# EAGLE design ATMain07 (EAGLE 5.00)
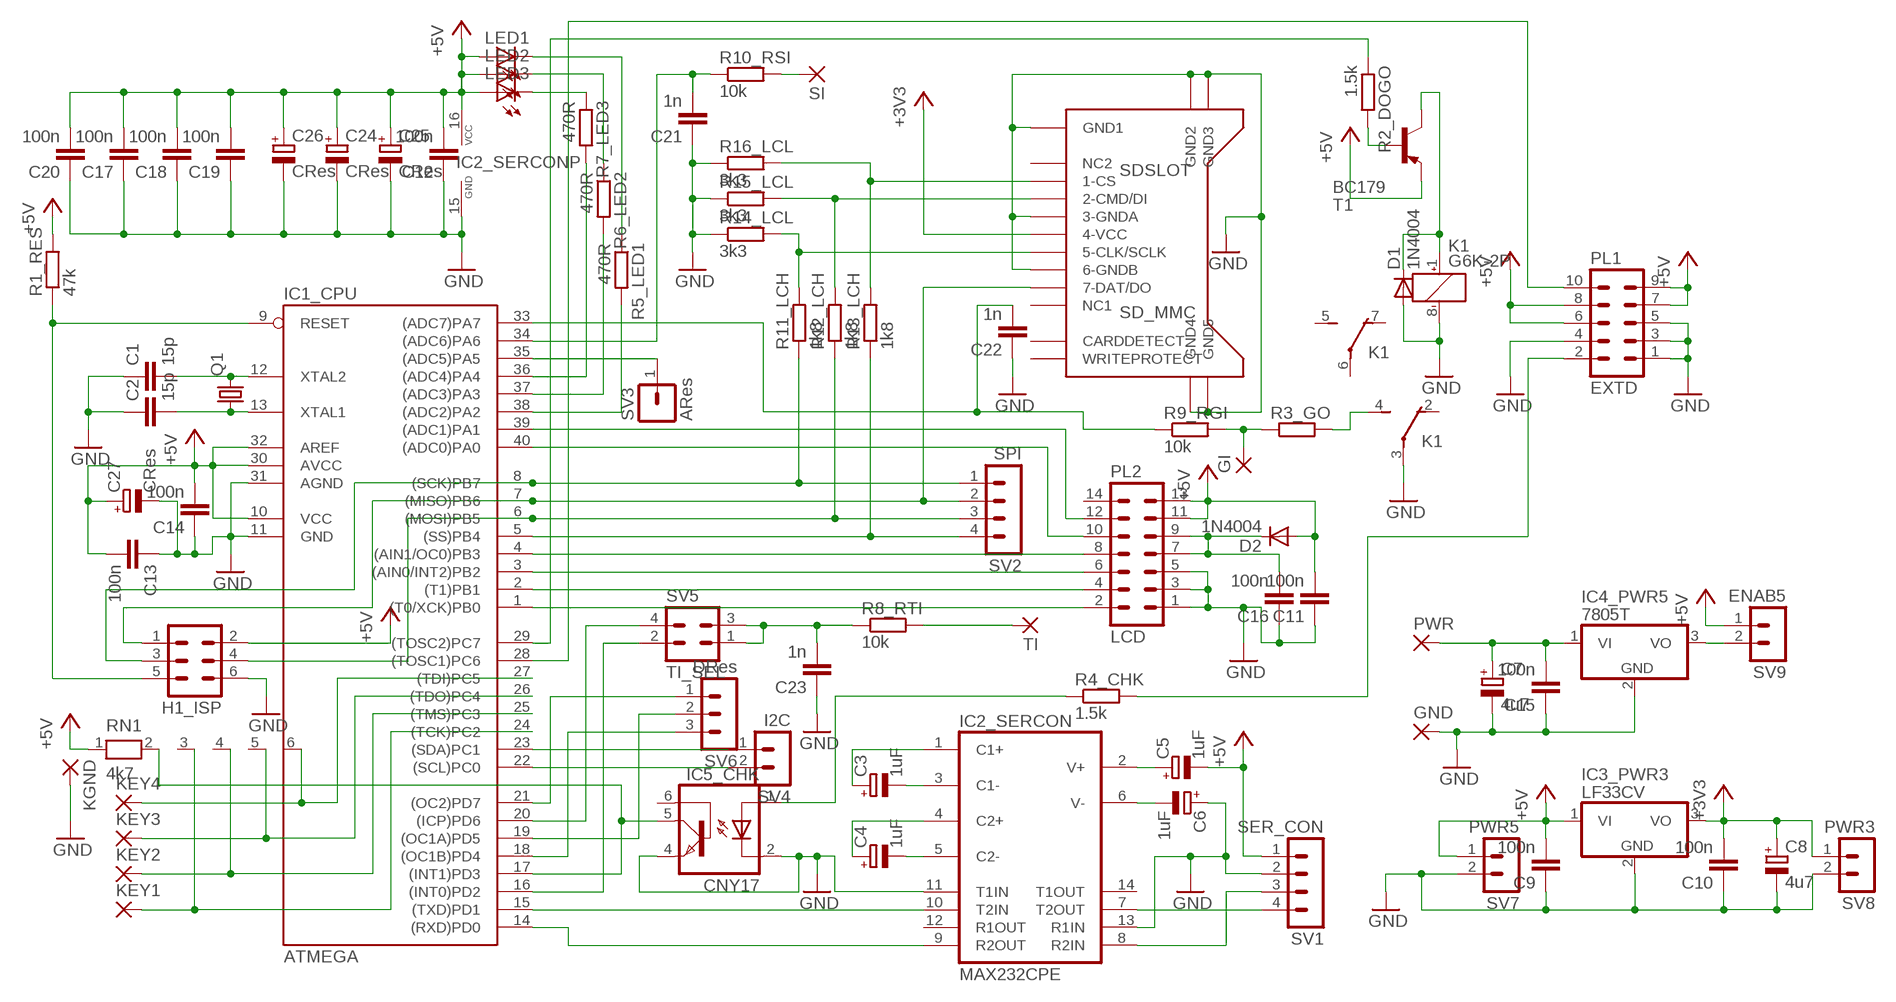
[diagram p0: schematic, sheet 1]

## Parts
C1  15p  C-EU025-025X050  [C025-025X050]
C2  15p  C-EU025-025X050  [C025-025X050]
C3  1uF  CPOL-EUE2-5  [E2-5]
C4  1uF  CPOL-EUE2-5  [E2-5]
C5  1uF  CPOL-EUE2-5  [E2-5]
C6  1uF  CPOL-EUE2-5  [E2-5]
C7  4u7  CPOL-EUE2-5  [E2-5]
C8  4u7  CPOL-EUE2-5  [E2-5]
C9  100n  C-EU025-025X050  [C025-025X050]
C10  100n  C-EU025-025X050  [C025-025X050]
C11  100n  C-EU025-025X050  [C025-025X050]
C12  100n  C-EU025-025X050  [C025-025X050]
C13  100n  C-EU025-025X050  [C025-025X050]
C14  100n  C-EU025-025X050  [C025-025X050]
C15  100n  C-EU025-025X050  [C025-025X050]
C16  100n  C-EU025-025X050  [C025-025X050]
C17  100n  C-EU025-025X050  [C025-025X050]
C18  100n  C-EU025-025X050  [C025-025X050]
C19  100n  C-EU025-025X050  [C025-025X050]
C20  100n  C-EU025-025X050  [C025-025X050]
C21  1n  C-EU025-025X050  [C025-025X050]
C22  1n  C-EU025-025X050  [C025-025X050]
C23  1n  C-EU025-025X050  [C025-025X050]
C24  CRes  CPOL-EUE2-5  [E2-5]
C25  CRes  CPOL-EUE2-5  [E2-5]
C26  CRes  CPOL-EUE2-5  [E2-5]
C27  CRes  CPOL-EUE2-5  [E2-5]
D1  1N4004  [DO41-10]
D2  1N4004  [DO41-10]
GI  2,54/1,0  [2,54/1,0]
GND  2,54/1,0  [2,54/1,0]
H1_ISP  MA03-2  [MA03-2]
IC1_CPU  ATMEGA  MEGA16-P  [DIL40]
IC2_SERCON  MAX232CPE  MAX232  [DIL16]
IC3_PWR3  LF33CV  7805T  [TO220H]
IC4_PWR5  7805T  [TO220H]
IC5_CHK  CNY17  [DIL06]
K1  G6K-2P  [G6K-2P]
KEY1  2,54/1,0  [2,54/1,0]
KEY2  2,54/1,0  [2,54/1,0]
KEY3  2,54/1,0  [2,54/1,0]
KEY4  2,54/1,0  [2,54/1,0]
KGND  2,54/1,0  [2,54/1,0]
LED1  BIGLED  [BIGLED]
LED2  BIGLED  [BIGLED]
LED3  BIGLED  [BIGLED]
PL1  EXTD  10V  [10V]
PL2  LCD  14V  [14V]
PWR  2,54/1,0  [2,54/1,0]
Q1  CRYTALHC49U-V  [HC49U-V]
R1_RES  47k  R-EU_0309/10  [0309/10]
R2_DOGO  1.5k  R-EU_0309/10  [0309/10]
R3_GO  R-EU_0309/10  [0309/10]
R4_CHK  1.5k  R-EU_0309/10  [0309/10]
R5_LED1  470R  R-EU_0309/10  [0309/10]
R6_LED2  470R  R-EU_0309/10  [0309/10]
R7_LED3  470R  R-EU_0309/10  [0309/10]
R8_RTI  10k  R-EU_0309/10  [0309/10]
R9_RGI  10k  R-EU_0309/10  [0309/10]
R10_RSI  10k  R-EU_0309/10  [0309/10]
R11_LCH  1k8  R-EU_0309/10  [0309/10]
R12_LCH  1k8  R-EU_0309/10  [0309/10]
R13_LCH  1k8  R-EU_0309/10  [0309/10]
R14_LCL  3k3  R-EU_0309/10  [0309/10]
R15_LCL  3k3  R-EU_0309/10  [0309/10]
R16_LCL  3k3  R-EU_0309/10  [0309/10]
RN1  4k7  RN05  [RN-6]
SDSLOT  SD_MMC  SD_MMCW_CARD  [SD_MMC-PACKAGE]
SI  2,54/1,0  [2,54/1,0]
SV1  SER_CON  MA04-1  [MA04-1]
SV2  SPI  MA04-1  [MA04-1]
SV3  ARes  MA01-1  [MA01-1]
SV4  I2C  MA02-1  [MA02-1]
SV5  TI_SEL  MA02-2  [MA02-2]
SV6  DRes  MA03-1  [MA03-1]
SV7  PWR5  MA02-1  [MA02-1]
SV8  PWR3  MA02-1  [MA02-1]
SV9  ENAB5  MA02-1  [MA02-1]
T1  BC179  [TO18]
TI  2,54/1,0  [2,54/1,0]

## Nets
+3V3: C8.+ C10.2 IC3_PWR3.3(VO) SDSLOT.P$4(4-VCC) SV8.1
+5V: C5.- C9.2 C11.2 C12.2 C13.2 C14.2 C17.2 C18.2 C19.2 C20.2 C24.+ C25.+ C26.+ C27.+ D2.A H1_ISP.2 IC1_CPU.10(VCC) IC1_CPU.30(AVCC) IC1_CPU.32(AREF) IC2_SERCON.16(VCC) IC3_PWR3.1(VI) LED1.A LED2.A LED3.A PL1.6 PL1.7 PL1.8 PL1.9 PL2.11 PL2.13 R1_RES.2 RN1.1 SV1.1 SV7.1 SV9.1 T1.1(E)
GND: C1.1 C2.1 C6.+ C7.- C8.- C9.1 C10.1 C11.1 C12.1 C13.1 C14.1 C15.1 C16.1 C17.1 C18.1 C19.1 C20.1 C21.1 C22.1 C23.1 C24.- C25.- C26.- C27.- D1.A GND.1(P) H1_ISP.6 IC1_CPU.11(GND) IC1_CPU.31(AGND) IC2_SERCON.11(T1IN) IC2_SERCON.13(R1IN) IC2_SERCON.15(GND) IC3_PWR3.2(GND) IC4_PWR5.2(GND) IC5_CHK.2(C) IC5_CHK.4(EMI) K1.3(2:P) K1.8(1:-) KGND.1(P) PL1.1 PL1.3 PL1.4 PL1.5 PL2.1 PL2.3 PL2.5 R14_LCL.1 R15_LCL.1 R16_LCL.1 SDSLOT.P$3(3-GNDA) SDSLOT.P$6(6-GNDB) SDSLOT.P$12(GND1) SDSLOT.P$13(GND2) SDSLOT.P$14(GND3) SDSLOT.P$15(GND4) SDSLOT.P$16(GND5) SV1.2 SV7.2 SV8.2
N$1: IC1_CPU.14((RXD)PD0) IC2_SERCON.9(R2OUT)
N$2: IC1_CPU.15((TXD)PD1) IC2_SERCON.10(T2IN)
N$3: IC4_PWR5.3(VO) SV9.2
N$4: IC1_CPU.37((ADC3)PA3) R6_LED2.2
N$5: IC1_CPU.38((ADC2)PA2) R5_LED1.2
N$6: C23.2 R8_RTI.1 SV5.1 SV5.3
N$7: C7.+ C15.2 IC4_PWR5.1(VI) PWR.1(P)
N$8: IC1_CPU.1((T0/XCK)PB0) PL2.2
N$9: IC1_CPU.2((T1)PB1) PL2.4
N$10: IC1_CPU.3((AIN0/INT2)PB2) PL2.6
N$11: IC1_CPU.4((AIN1/OC0)PB3) PL2.8
N$12: IC1_CPU.40((ADC0)PA0) PL2.10
N$13: IC1_CPU.39((ADC1)PA1) PL2.12
N$14: GI.1(P) R3_GO.1 R9_RGI.2
N$15: H1_ISP.1 IC1_CPU.7((MISO)PB6) SDSLOT.P$7(7-DAT/DO) SV2.2
N$16: H1_ISP.4 IC1_CPU.6((MOSI)PB5) R12_LCH.1 SV2.3
N$17: H1_ISP.3 IC1_CPU.8((SCK)PB7) R11_LCH.1 SV2.1
N$18: H1_ISP.5 IC1_CPU.9(RESET) R1_RES.1
N$19: LED3.K(C) R7_LED3.1
N$20: IC1_CPU.21((OC2)PD7) SV6.1
N$21: IC1_CPU.35((ADC5)PA5) SV3.1
N$22: IC1_CPU.16((INT0)PD2) SV5.2
N$23: IC1_CPU.20((ICP)PD6) SV5.4
N$24: IC1_CPU.27((TDI)PC5) KEY4.1(P) RN1.6
N$25: C21.2 IC1_CPU.34((ADC6)PA6) R10_RSI.1
N$27: K1.4(2:S) R3_GO.2
N$28: R10_RSI.2 SI.1(P)
N$29: IC1_CPU.26((TDO)PC4) KEY3.1(P) RN1.5
N$31: IC1_CPU.29((TOSC2)PC7) R2_DOGO.1
N$33: IC1_CPU.28((TOSC1)PC6) PL1.10
N$34: IC1_CPU.25((TMS)PC3) KEY2.1(P) RN1.4
N$35: IC1_CPU.24((TCK)PC2) KEY1.1(P) RN1.3
N$36: IC1_CPU.5((SS)PB4) R13_LCH.1 SV2.4
N$37: R11_LCH.2 R14_LCL.2 SDSLOT.P$5(5-CLK/SCLK)
N$38: C1.2 IC1_CPU.12(XTAL2) Q1.2
N$39: C2.2 IC1_CPU.13(XTAL1) Q1.1
N$41: R12_LCH.2 R15_LCL.2 SDSLOT.P$2(2-CMD/DI)
N$42: IC1_CPU.22((SCL)PC0) SV4.2
N$43: IC1_CPU.23((SDA)PC1) SV4.1
N$44: R8_RTI.2 TI.1(P)
N$45: IC1_CPU.36((ADC4)PA4) R7_LED3.2
N$46: R13_LCH.2 R16_LCL.2 SDSLOT.P$1(1-CS)
N$47: IC1_CPU.19((OC1A)PD5) SV6.2
N$48: IC1_CPU.18((OC1B)PD4) SV6.3
N$50: PL1.2 R4_CHK.2
N$51: C16.2 D2.C PL2.7 PL2.9
N$54: C3.+ IC2_SERCON.1(C1+)
N$55: C3.- IC2_SERCON.3(C1-)
N$56: C4.+ IC2_SERCON.4(C2+)
N$57: C4.- IC2_SERCON.5(C2-)
N$58: C5.+ IC2_SERCON.2(V+)
N$59: C6.- IC2_SERCON.6(V-)
N$60: C22.2 IC1_CPU.33((ADC7)PA7) R9_RGI.1
N$61: LED2.K(C) R6_LED2.1
N$62: R2_DOGO.2 T1.2(B)
N$63: D1.C K1.1(1:+) T1.3(C)
N$69: LED1.K(C) R5_LED1.1
N$70: IC2_SERCON.7(T2OUT) SV1.4
N$71: IC2_SERCON.8(R2IN) SV1.3
N$74: IC5_CHK.1(A) R4_CHK.1
N$75: IC1_CPU.17((INT1)PD3) IC5_CHK.5(COL) RN1.2
Unconnected: IC2_SERCON.12(R1OUT) IC2_SERCON.14(T1OUT) IC5_CHK.6(BAS) K1.2(2:O) K1.5(3:S) K1.6(3:P) K1.7(3:O) PL2.14 SDSLOT.P$8(NC1) SDSLOT.P$9(NC2) SDSLOT.P$10(CARDDETECT) SDSLOT.P$11(WRITEPROTECT)

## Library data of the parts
C1 C2 C9-C23 = smf:C-EU: CAPACITOR, European symbol
C3-C8 C24-C27 = smf:CPOL-EU: POLARIZED CAPACITOR, European symbol
D1 D2 = smf:1N4004: DIODE
GI GND KEY1-KEY4 KGND PWR SI TI = smf:2,54/1,0: THROUGH-HOLE PAD
H1_ISP = smf:MA03-2: PIN HEADER
IC1_CPU = smf:MEGA16-P: MICROCONTROLLER 16 Kbytes FLASH 1 kbytes SRAM 512 bytes EEPROM USART 8-channel 10 bit ADC Source: avr.lbr
IC2_SERCON = smf:MAX232: RS232 TRANSEIVER
IC3_PWR3 IC4_PWR5 = smf:78*: Positive VOLTAGE REGULATOR Source: http://cache.national.com/ds/LM/LM78L05.pdf http://www.fairchildsemi.com/ds/LM/LM7805.pdf
IC5_CHK = smf:CNY17: SIEMENS OPTO COUPLER
K1 = smf:G6K: Low Signal Relay oeiwcsnts1.omron.com/.. D20G6K0100.pdf
LED1-LED3 = smf:BIGLED: Big LED
PL1 = smf:10V: CONNECTOR
PL2 = smf:14V: CONNECTOR
Q1 = smf:CRYTAL: CRYSTAL
R1_RES R2_DOGO R3_GO R4_CHK R5_LED1 R6_LED2 R7_LED3 R8_RTI R9_RGI R10_RSI R11_LCH R12_LCH R13_LCH R14_LCL R15_LCL R16_LCL = smf:R-EU_: RESISTOR, European symbol
RN1 = smf:RN05: RESISTOR NETWORK
SDSLOT = smf:SD_MMC
SV1 SV2 = smf:MA04-1: PIN HEADER
SV3 = smf:MA01-1
SV4 SV7-SV9 = smf:MA02-1
SV5 = smf:MA02-2
SV6 = smf:MA03-1: PIN HEADER
T1 = smf:BC179: PNP Transistor

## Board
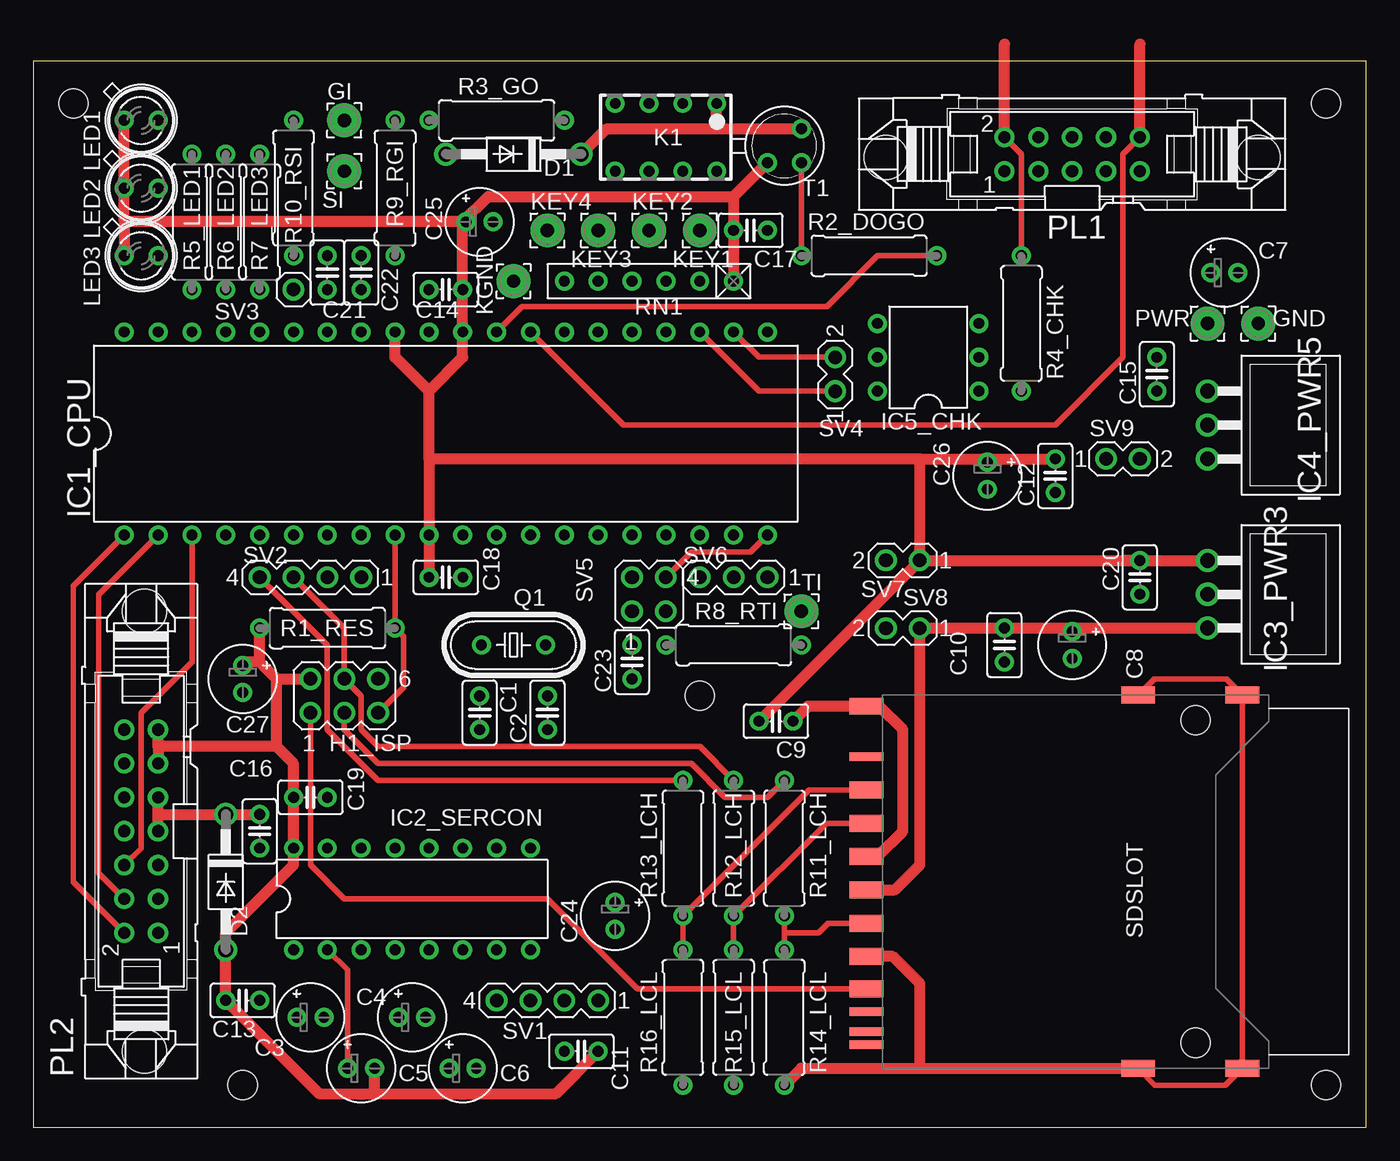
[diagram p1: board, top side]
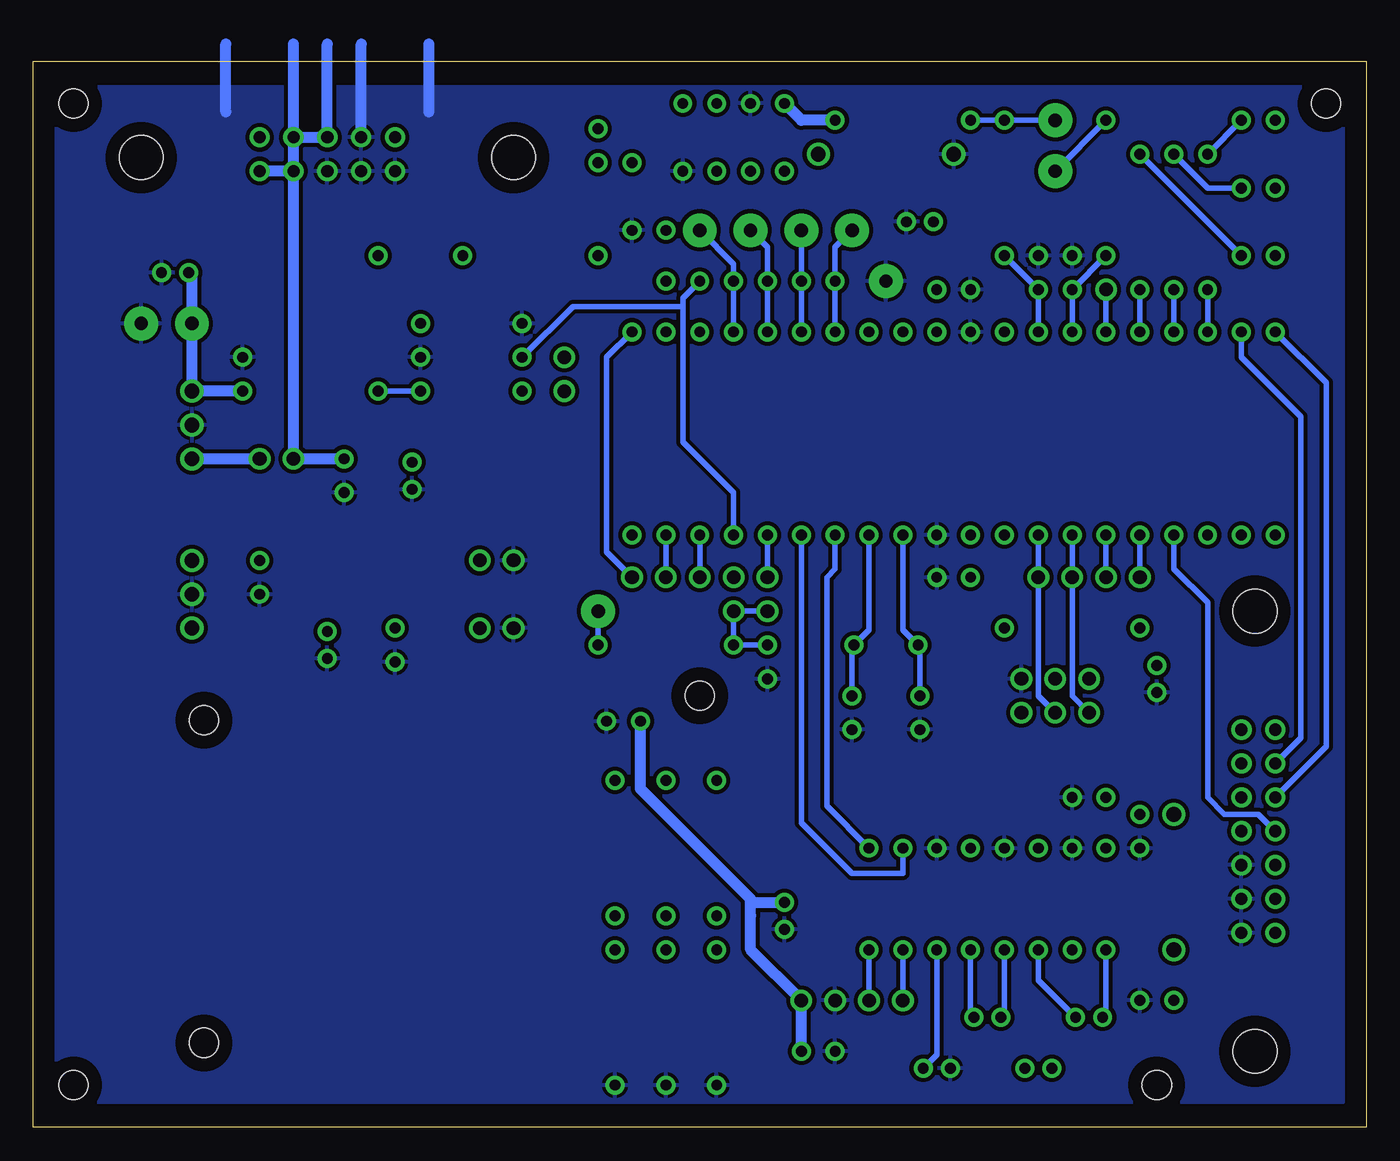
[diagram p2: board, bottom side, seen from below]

Size 100 x 80 mm. Coordinates in mm from the lower left corner, seen from the top.
Outline: 0,0 100,0 100,80 0,80 0,0
Copper layers (1*16): Top 0.035mm / dielectric 1.5mm / Bottom 0.035mm
Design rules "default *": minimum track width 16mil, minimum drill 24mil, track to track 12mil, track to pad 10mil, pad to pad 12mil, via to via 12mil, smd to smd 8mil, copper to edge 40mil, drill to drill 16mil, minimum pad ring 12mil, minimum via ring 8mil, stop-mask expansion 4mil, vias tented up to drill 0mil, thermal gap 10mil
Holes 2.2 mm at 15.71,3.17 3.01,76.83 50,32.38 96.99,3.17 96.99,76.83

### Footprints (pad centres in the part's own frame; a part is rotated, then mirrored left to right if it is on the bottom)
C025-025X050 = drill 0.813 round: 1 -1.27,0; 2 1.27,0
E2-5 = drill 0.813 pad 1.27 round: + -1.016,0; - 1.016,0
DO41-10 = drill 1.118 round: A 5.08,0; C -5.08,0
2,54/1,0 = drill 1 pad 2.54 round: 1 0,0
MA03-2 = drill 1.016 round: 1 -2.54,-1.27; 2 -2.54,1.27; 3 0,-1.27; 4 0,1.27; 5 2.54,-1.27; 6 2.54,1.27
DIL40 = drill 0.813 round: 1 -24.13,-7.62; 2 -21.59,-7.62; 3 -19.05,-7.62; 4 -16.51,-7.62; 5 -13.97,-7.62; 6 -11.43,-7.62; 7 -8.89,-7.62; 8 -6.35,-7.62; 9 -3.81,-7.62; 10 -1.27,-7.62; 11 1.27,-7.62; 12 3.81,-7.62; 13 6.35,-7.62; 14 8.89,-7.62; 15 11.43,-7.62; 16 13.97,-7.62; 17 16.51,-7.62; 18 19.05,-7.62; 19 21.59,-7.62; 20 24.13,-7.62; 21 24.13,7.62; 22 21.59,7.62; 23 19.05,7.62; 24 16.51,7.62; 25 13.97,7.62; 26 11.43,7.62; 27 8.89,7.62; 28 6.35,7.62; 29 3.81,7.62; 30 1.27,7.62; 31 -1.27,7.62; 32 -3.81,7.62; 33 -6.35,7.62; 34 -8.89,7.62; 35 -11.43,7.62; 36 -13.97,7.62; 37 -16.51,7.62; 38 -19.05,7.62; 39 -21.59,7.62; 40 -24.13,7.62
DIL16 = drill 0.813 round: 1 -8.89,-3.81; 2 -6.35,-3.81; 3 -3.81,-3.81; 4 -1.27,-3.81; 5 1.27,-3.81; 6 3.81,-3.81; 7 6.35,-3.81; 8 8.89,-3.81; 9 8.89,3.81; 10 6.35,3.81; 11 3.81,3.81; 12 1.27,3.81; 13 -1.27,3.81; 14 -3.81,3.81; 15 -6.35,3.81; 16 -8.89,3.81
TO220H = drill 1.118 round: 1 -2.54,-10.16; 2 0,-10.16; 3 2.54,-10.16
DIL06 = drill 0.813 round: 1 -2.54,-3.81; 2 0,-3.81; 3 2.54,-3.81; 4 2.54,3.81; 5 0,3.81; 6 -2.54,3.81
G6K-2P = drill 0.8 round: 1 -2.54,-2.54; 2 0,-2.54; 3 2.54,-2.54; 4 5.08,-2.54; 5 5.08,2.54; 6 2.54,2.54; 7 0,2.54; 8 -2.54,2.54
BIGLED = drill 0.813 round: A -1.27,0; K 1.27,0
10V = drill 0.914 round: 1 -5.08,-1.27; 2 -5.08,1.27; 3 -2.54,-1.27; 4 -2.54,1.27; 5 0,-1.27; 6 0,1.27; 7 2.54,-1.27; 8 2.54,1.27; 9 5.08,-1.27; 10 5.08,1.27 | hole 3.302: 13.97,-0.254; -13.97,-0.254
14V = drill 0.914 round: 1 -7.62,-1.27; 2 -7.62,1.27; 3 -5.08,-1.27; 4 -5.08,1.27; 5 -2.54,-1.27; 6 -2.54,1.27; 7 0,-1.27; 8 0,1.27; 9 2.54,-1.27; 10 2.54,1.27; 11 5.08,-1.27; 12 5.08,1.27; 13 7.62,-1.27; 14 7.62,1.27 | hole 3.302: 16.51,-0.254; -16.51,-0.254
HC49U-V = drill 0.813 round: 1 -2.413,0; 2 2.413,0
0309/10 = drill 0.813 round: 1 -5.08,0; 2 5.08,0
RN-6 = drill 0.813 round: 1 -6.35,0; 2 -3.81,0; 3 -1.27,0; 4 1.27,0; 5 3.81,0; 6 6.35,0
SD_MMC-PACKAGE = smd 2.54 x 1.27: P$1 -0.2,20.88; P$2 -0.2,18.38; P$3 -0.2,15.88; P$4 -0.2,13.38; P$5 -0.2,10.88; P$6 -0.2,8.38; P$7 -0.2,5.95; P$12 -0.2,27.16; P$13 20.19,0; P$14 20.19,28; P$15 28,28; P$16 28,0 | smd 2.54 x 0.635: P$8 -0.2,4.26; P$9 -0.2,23.38; P$10 -0.2,2.76; P$11 -0.2,1.76 | hole 2.2: 24.508,1.9; 24.508,26.1
MA04-1 = drill 1.016 round: 1 -3.81,0; 2 -1.27,0; 3 1.27,0; 4 3.81,0
MA01-1 = drill 1.016 round: 1 0,0
MA02-1 = drill 1.016 round: 1 -1.27,0; 2 1.27,0
MA02-2 = drill 1.016 round: 1 -1.27,-1.27; 2 -1.27,1.27; 3 1.27,-1.27; 4 1.27,1.27
MA03-1 = drill 1.016 round: 1 -2.54,0; 2 0,0; 3 2.54,0
TO18 = drill 0.813 round: 1 -1.27,-1.27; 2 1.27,-1.27; 3 1.27,1.27

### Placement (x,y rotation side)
C1  33.49,31.11 90 top
C2  38.57,31.11 90 top
C3  20.79,8.25 0 top
C4  28.41,8.25 0 top
C5  24.6,4.44 0 top
C6  32.22,4.44 0 top
C7  89.37,64.13 0 top
C8  77.94,36.19 270 top
C9  55.72,30.48 180 top
C10  72.86,36.19 90 top
C11  41.11,5.71 0 top
C12  76.67,48.89 90 top
C13  15.71,9.52 180 top
C14  30.95,62.86 0 top
C15  84.29,56.51 270 top
C16  16.98,22.22 90 top
C17  53.81,67.31 180 top
C18  30.95,41.27 180 top
C19  20.79,24.76 180 top
C20  83.02,41.27 90 top
C21  22.06,64.13 270 top
C22  24.6,64.13 270 top
C23  44.92,34.92 90 top
C24  43.65,15.87 270 top
C25  33.49,67.94 0 top
C26  71.59,48.89 270 top
C27  15.71,33.65 270 top
D1  36.03,73.02 180 top
D2  14.44,18.41 270 top
GI  23.33,75.56 0 top
GND  91.91,60.32 0 top
H1_ISP  23.33,32.38 0 top
IC1_CPU  30.95,52.06 0 top
IC2_SERCON  28.41,17.14 0 top
IC3_PWR3  98.26,40 270 top
IC4_PWR5  98.26,52.7 270 top
IC5_CHK  67.14,57.78 90 top
K1  48.73,74.29 180 top
KEY1  50,67.31 0 top
KEY2  46.19,67.31 0 top
KEY3  42.38,67.31 0 top
KEY4  38.57,67.31 0 top
KGND  36.03,63.49 0 top
LED1  8.09,75.56 0 top
LED2  8.09,70.48 0 top
LED3  8.09,65.4 0 top
PL1  77.94,73.02 0 top
PL2  8.09,22.22 90 top
PWR  88.1,60.32 0 top
Q1  36.03,36.19 180 top
R1_RES  22.06,37.46 180 top
R2_DOGO  62.7,65.4 180 top
R3_GO  34.76,75.56 0 top
R4_CHK  74.13,60.32 90 top
R5_LED1  11.9,67.94 270 top
R6_LED2  14.44,67.94 270 top
R7_LED3  16.98,67.94 270 top
R8_RTI  52.54,36.19 0 top
R9_RGI  27.14,70.48 90 top
R10_RSI  19.52,70.48 90 top
R11_LCH  56.35,20.95 270 top
R12_LCH  52.54,20.95 270 top
R13_LCH  48.73,20.95 270 top
R14_LCL  56.35,8.25 90 top
R15_LCL  52.54,8.25 90 top
R16_LCL  48.73,8.25 90 top
RN1  46.19,63.49 180 top
SDSLOT  62.7,4.44 0 top
SI  23.33,71.75 0 top
SV1  38.57,9.52 180 top
SV2  20.79,41.27 180 top
SV3  19.52,62.86 0 top
SV4  60.16,56.51 90 top
SV5  46.19,40 0 top
SV6  52.54,41.27 180 top
SV7  65.24,42.54 180 top
SV8  65.24,37.46 180 top
SV9  81.75,50.16 0 top
T1  56.35,73.66 0 top
TI  57.62,38.73 0 top

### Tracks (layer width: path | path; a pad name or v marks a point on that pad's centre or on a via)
+3V3
  Top 0.813: SDSLOT.P$4 64.65,17.82 66.51,19.68 SV8.1 C10.2 77.94,37.46 | 77.94,37.46 IC3_PWR3.3 | 77.94,37.46 C8.+
+5V
  Top 0.813: 9.36,28.57 PL2.11 | 9.36,28.57 PL2.13 | C18.2 IC1_CPU.10 29.68,50.16 | 25.87,2.54 21.43,2.54 C13.2 D2.A 14.44,14.6 19.52,19.68 IC2_SERCON.16 C19.2 19.52,27.3 18.25,28.57 | 25.87,2.54 39.2,2.54 C11.2 | C5.- 25.62,2.54 25.87,2.54 | 29.68,50.16 29.68,55.24 | 29.68,55.24 27.14,57.78 IC1_CPU.32 | 32.22,67.94 C14.2 IC1_CPU.30 32.22,57.78 29.68,55.24 | SV7.1 C20.2 | C20.2 IC3_PWR3.1 | C9.2 SV7.1 | 18.25,28.57 18.25,33.65 | 18.25,33.65 16.98,34.92 | 16.98,34.92 R1_RES.2 | 18.25,33.65 H1_ISP.2 | 18.25,28.57 9.36,28.57 | C27.+ 15.96,34.92 16.98,34.92 | C20.2 81.75,42.54 | 32.22,67.94 34.12,69.84 52.54,69.84 | 52.54,69.84 T1.1 | 52.54,69.84 C17.2 RN1.1 | 66.51,50.16 29.68,50.16 | 66.51,50.16 71.59,50.16 | 71.59,50.16 C12.2 | 71.59,50.16 C26.+ | 32.22,67.94 6.82,67.94 | SV7.1 66.51,50.16 | LED1.A LED2.A 6.82,67.94 | 6.82,67.94 LED3.A | 32.22,67.94 C25.+
  Bottom 0.813: C11.2 SV1.1 46.19,13.33 46.19,15.87 | C9.2 54.45,25.39 46.19,17.14 46.19,15.87 | C24.+ 46.19,16.89 46.19,15.87 | PL1.8 PL1.6 77.94,81.28 | PL1.7 PL1.8 | PL1.7 PL1.9 | PL1.7 SV9.1 C12.2 | PL1.8 80.48,81.28
GND
  Top 0.406: SDSLOT.P$12 59.38,31.6 | SDSLOT.P$13 84.16,3.17 89.43,3.17 SDSLOT.P$16 | SDSLOT.P$16 SDSLOT.P$15 89.49,33.65 84.1,33.65 SDSLOT.P$14 | SDSLOT.P$16 90.64,4.44
  Top 0.813: C9.1 58.11,31.6 SDSLOT.P$12 63.48,31.6 65.24,29.84 65.24,22.22 63.34,20.32 SDSLOT.P$3 | SDSLOT.P$6 64.48,12.82 66.51,10.79 66.51,4.44 | 66.51,4.44 57.62,4.44 R14_LCL.1 | 66.51,4.44 SDSLOT.P$13
  Bottom 0.813: PL1.4 75.4,81.28 | 70.32,76.2 70.32,81.28 | 85.56,76.2 85.56,81.28
  pour Bottom (isolate 0.305): 1.74,78.1 1.74,1.9 98.26,1.9 98.26,78.1
N$1
  Bottom 0.406: IC1_CPU.14 39.84,41.9 40.48,41.27 40.48,24.12 IC2_SERCON.9
N$2
  Bottom 0.406: IC1_CPU.15 42.38,22.86 38.57,19.05 34.76,19.05 IC2_SERCON.10
N$3
  Bottom 0.813: SV9.2 IC4_PWR5.3
N$4
  Bottom 0.406: IC1_CPU.37 R6_LED2.2
N$5
  Bottom 0.406: IC1_CPU.38 R5_LED1.2
N$6
  Bottom 0.406: C23.2 R8_RTI.1 SV5.3 SV5.1
N$7
  Bottom 0.813: C15.2 IC4_PWR5.1 PWR.1 88.1,64.13 C7.+
N$8
  Top 0.406: PL2.2 3.01,18.41 3.01,40.63 IC1_CPU.1
N$9
  Top 0.406: IC1_CPU.2 4.92,40 4.92,19.05 PL2.4
N$10
  Top 0.406: IC1_CPU.3 11.9,34.92 8.09,31.11 8.09,20.95 PL2.6
N$11
  Bottom 0.406: IC1_CPU.4 14.44,41.9 11.9,39.36 11.9,24.76 10.63,23.49 8.09,23.49 PL2.8
N$12
  Bottom 0.406: IC1_CPU.40 3.01,55.88 3.01,28.57 PL2.10
N$13
  Bottom 0.406: IC1_CPU.39 9.36,57.78 4.92,53.34 4.92,29.21 PL2.12
N$14
  Bottom 0.406: GI.1 R9_RGI.2 R3_GO.1
N$15
  Top 0.406: H1_ISP.1 20.79,19.68 23.33,17.14 38.57,17.14 45.32,10.39 SDSLOT.P$7
  Bottom 0.406: IC1_CPU.7 SV2.2 22.06,32.38 H1_ISP.1
N$16
  Top 0.406: SV2.3 23.33,37.46 H1_ISP.4 24.6,32.38 24.6,29.84 25.87,28.57 50,28.57 R12_LCH.1
  Bottom 0.406: SV2.3 IC1_CPU.6
N$17
  Top 0.406: R11_LCH.1 55.08,24.76 51.91,24.76 49.37,27.3 25.87,27.3 23.33,29.84 H1_ISP.3
  Bottom 0.406: IC1_CPU.8 SV2.1 24.6,32.38 H1_ISP.3
N$18
  Top 0.406: IC1_CPU.9 R1_RES.1 27.78,36.82 27.78,33.02 H1_ISP.5
N$19
  Bottom 0.406: LED3.K R7_LED3.1
N$20
  Bottom 0.406: SV6.1 56.98,43.17 56.98,57.78 IC1_CPU.21
N$21
  Bottom 0.406: IC1_CPU.35 SV3.1
N$22
  Bottom 0.406: SV5.2 IC1_CPU.16
N$23
  Top 0.406: SV5.4 49.37,43.17 53.81,43.17 IC1_CPU.20
N$24
  Bottom 0.406: IC1_CPU.27 RN1.6 39.84,66.04 KEY4.1
N$25
  Bottom 0.406: IC1_CPU.34 C21.2 R10_RSI.1
N$27
  Bottom 0.813: K1.4 42.38,75.56 R3_GO.2
N$28
  Bottom 0.406: R10_RSI.2 SI.1
N$29
  Bottom 0.406: IC1_CPU.26 RN1.5 KEY3.1
N$31
  Top 0.406: IC1_CPU.29 36.66,61.59 59.52,61.59 63.34,65.4 R2_DOGO.1
N$33
  Top 0.406: IC1_CPU.28 44.29,52.7 76.67,52.7 81.75,57.78 81.75,73.02 PL1.10
  Top 0.813: PL1.10 83.02,81.28
N$34
  Bottom 0.406: IC1_CPU.25 RN1.4 44.92,66.04 KEY2.1
N$35
  Bottom 0.406: IC1_CPU.24 RN1.3 47.46,64.77 KEY1.1
N$36
  Top 0.406: R13_LCH.1 25.87,26.03 22.06,29.84 22.06,36.19 SV2.4
  Bottom 0.406: SV2.4 IC1_CPU.5
N$37
  Top 0.406: 56.35,14.6 R11_LCH.2 | R14_LCL.2 56.35,14.6 | 56.35,14.6 56.35,15.32 | SDSLOT.P$5 59.61,15.32 58.89,14.6 56.35,14.6
N$38
  Bottom 0.406: IC1_CPU.12 34.76,37.33 Q1.2 33.49,36.06 C1.2
N$39
  Bottom 0.406: IC1_CPU.13 37.3,37.33 Q1.1 38.57,36.06 C2.2
N$41
  Top 0.406: R15_LCL.2 R12_LCH.2 59.49,22.82 SDSLOT.P$2
N$42
  Top 0.406: IC1_CPU.22 54.45,57.78 SV4.2
N$43
  Top 0.406: IC1_CPU.23 54.45,55.24 SV4.1
N$44
  Bottom 0.406: R8_RTI.2 TI.1
N$45
  Bottom 0.406: IC1_CPU.36 R7_LED3.2
N$46
  Top 0.406: 56.35,23.49 R13_LCH.2 R16_LCL.2 | 56.35,23.49 56.91,24.05 | SDSLOT.P$1 58.18,25.32 56.35,23.49
N$47
  Bottom 0.406: SV6.2 IC1_CPU.19
N$48
  Bottom 0.406: SV6.3 IC1_CPU.18
N$50
  Top 0.406: R4_CHK.2 74.13,73.02 PL1.2
  Top 0.813: PL1.2 72.86,81.28
N$51
  Top 0.813: PL2.7 9.36,23.49 | 9.36,23.49 PL2.9 | 9.36,23.49 D2.C C16.2
N$54
  Bottom 0.406: C3.+ 19.52,8.5 IC2_SERCON.1
N$55
  Bottom 0.406: C3.- 24.6,11.04 IC2_SERCON.3
N$56
  Bottom 0.406: C4.+ 27.14,8.5 IC2_SERCON.4
N$57
  Bottom 0.406: C4.- 29.68,8.5 IC2_SERCON.5
N$58
  Top 0.406: C5.+ 23.58,11.81 IC2_SERCON.2
N$59
  Bottom 0.406: C6.- 32.22,5.46 IC2_SERCON.6
N$60
  Bottom 0.406: IC1_CPU.33 C22.2 R9_RGI.1
N$61
  Bottom 0.406: R6_LED2.1 11.9,70.48 LED2.K
N$62
  Top 0.406: R2_DOGO.2 T1.2
N$63
  Top 0.813: D1.C 43.02,74.93 51.27,74.93 | 51.27,74.93 T1.3 | 51.27,74.93 K1.1
N$69
  Bottom 0.406: LED1.K R5_LED1.1
N$70
  Bottom 0.406: SV1.4 IC2_SERCON.7
N$71
  Bottom 0.406: SV1.3 IC2_SERCON.8
N$74
  Bottom 0.406: IC5_CHK.1 R4_CHK.1
N$75
  Bottom 0.406: RN1.2 51.27,62.22 51.27,61.59 | 51.27,61.59 51.27,51.43 47.46,47.62 IC1_CPU.17 | IC5_CHK.5 59.52,61.59 51.27,61.59

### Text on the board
tDocu: smfATDemoMain1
